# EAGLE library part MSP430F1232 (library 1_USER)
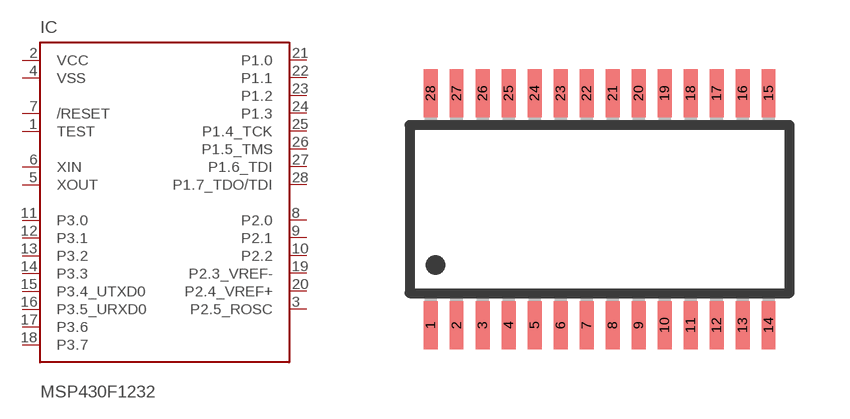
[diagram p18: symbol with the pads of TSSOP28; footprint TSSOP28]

Designator prefix IC

## MSP430F1232  [TSSOP28]
1  TEST  in
2  VCC  pwr
3  P2.5_ROSC
4  VSS  pwr
5  XOUT
6  XIN  in
7  /RESET  in
8  P2.0
9  P2.1
10  P2.2
11  P3.0
12  P3.1
13  P3.2
14  P3.3
15  P3.4_UTXD0
16  P3.5_URXD0
17  P3.6
18  P3.7
19  P2.3_VREF-
20  P2.4_VREF+
21  P1.0
22  P1.1
23  P1.2
24  P1.3
25  P1.4_TCK
26  P1.5_TMS
27  P1.6_TDI
28  P1.7_TDO/TDI

## Footprint TSSOP28 (pad centres in mm)
28-Lead TSSOP Package RU-28
smd 0.35 x 1.2: 1 -4.225,-2.9; 2 -3.575,-2.9; 3 -2.925,-2.9; 4 -2.275,-2.9; 5 -1.625,-2.9; 6 -0.975,-2.9; 7 -0.325,-2.9; 8 0.325,-2.9; 9 0.975,-2.9; 10 1.625,-2.9; 11 2.275,-2.9; 12 2.925,-2.9; 13 3.575,-2.9; 14 4.225,-2.9; 15 4.225,2.9; 16 3.575,2.9; 17 2.925,2.9; 18 2.275,2.9; 19 1.625,2.9; 20 0.975,2.9; 21 0.325,2.9; 22 -0.325,2.9; 23 -0.975,2.9; 24 -1.625,2.9; 25 -2.275,2.9; 26 -2.925,2.9; 27 -3.575,2.9; 28 -4.225,2.9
